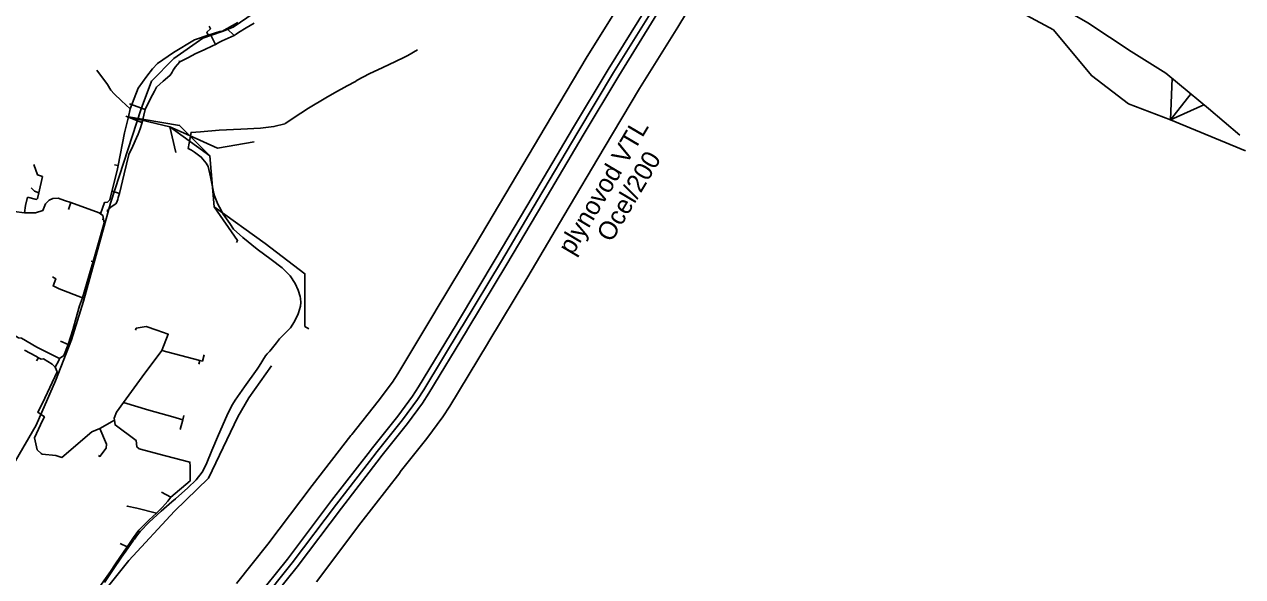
# Model space of a CAD drawing. Extents: x -555222 to -543220, y -1067119 to -1030889.
# Drawn here: x -550267 to -549473, y -1043672 to -1043312 of the extents above; entities that cross this region are included whole.
import ezdxf

# ---------------------------------------------------------------- set-up
doc = ezdxf.new("R2010")
doc.units = 0
for name, color, linetype in [('07_ELEKTRO', 7, 'Continuous'), ('07_KANALIZACE', 7, 'Continuous'), ('07_OCH_P A POPISY TI', 7, 'Continuous'), ('07_PLYNOVOD', 7, 'Continuous'), ('07_SDĚLOVACÍ', 7, 'Continuous'), ('07_VODOVOD', 7, 'Continuous')]:
    doc.layers.add(name, color=color, linetype=linetype)

msp = doc.modelspace()

# ---------------------------------------------------------------- linework, layer by layer
at = {"layer": '07_ELEKTRO'}
for points in [[(-549974.12, -1042947.84), (-549966.71, -1042973.14), (-549959.13, -1042998.29), (-549951.55, -1043025.99), (-549938.72, -1043036.58), (-549925.88, -1043047.17), (-549906.25, -1043065.21), (-549889.53, -1043077.11), (-549868.18, -1043096.69), (-549836.5, -1043125.51), (-549825.59, -1043135.37), (-549800.93, -1043157.41), (-549779.18, -1043176.38), (-549760.4, -1043193.19), (-549743.2, -1043209.09), (-549711.9, -1043227.06), (-549634.41, -1043269.38), (-549598.14, -1043296.84), (-549573.72, -1043310.9), (-549545.44, -1043329.57), (-549522.84, -1043343.61), (-549507.68, -1043356.25), (-549494.98, -1043366.73), (-549474.61, -1043384.22)], [(-550238.32, -1043706.58), (-550213.9, -1043688.03), (-550213.72, -1043680.02), (-550198.94, -1043661.37), (-550169.12, -1043629.26), (-550146.86, -1043607.87), (-550127.82, -1043567.81), (-550120.72, -1043555.47), (-550105.91, -1043534.57)]]:
    msp.add_lwpolyline(points, dxfattribs=at)
at = {"layer": '07_KANALIZACE'}
msp.add_lwpolyline([(-550272.8, -1043596.48), (-550259.34, -1043573.29), (-550246.63, -1043544.31), (-550236.16, -1043517.57), (-550228.38, -1043492.44), (-550210.77, -1043428.47), (-550190.76, -1043367.05), (-550184.19, -1043348.9), (-550169.51, -1043334.1), (-550150.59, -1043320.84), (-550138.09, -1043316.48), (-550130.78, -1043313.61), (-550098.73, -1043291.61)], dxfattribs=at)
at = {"layer": '07_OCH_P A POPISY TI'}
for p, q in [((-549812.12, -1043265.35), (-549840.9, -1043313.64)), ((-549900.02, -1043332.91), (-549875.06, -1043292.82)), ((-549886.36, -1043341.24), (-549861.4, -1043301.15)), ((-549854.56, -1043305.31), (-549879.52, -1043345.4)), ((-549840.9, -1043313.64), (-549865.86, -1043353.73)), ((-549923.29, -1043371.9), (-549900.02, -1043332.91)), ((-549909.54, -1043380.08), (-549886.36, -1043341.24)), ((-549879.52, -1043345.4), (-549902.66, -1043384.16)), ((-549865.86, -1043353.73), (-549888.91, -1043392.34)), ((-549949.61, -1043416.37), (-549923.29, -1043371.9)), ((-549935.85, -1043424.53), (-549909.54, -1043380.08)), ((-549902.66, -1043384.16), (-549928.97, -1043428.61)), ((-549888.91, -1043392.34), (-549915.21, -1043436.77)), ((-549973.12, -1043455.93), (-549949.61, -1043416.37)), ((-549959.38, -1043464.13), (-549935.85, -1043424.53)), ((-549928.97, -1043428.61), (-549952.52, -1043468.23)), ((-549915.21, -1043436.77), (-549938.78, -1043476.43)), ((-549998.44, -1043498.12), (-549973.12, -1043455.93)), ((-549984.71, -1043506.34), (-549959.38, -1043464.13)), ((-549952.52, -1043468.23), (-549977.85, -1043510.44)), ((-549938.78, -1043476.43), (-549964.12, -1043518.66)), ((-550023.55, -1043539.66), (-549999.3, -1043499.56)), ((-549999.3, -1043499.56), (-549998.44, -1043498.12)), ((-550009.97, -1043548.12), (-549985.58, -1043507.79)), ((-549985.58, -1043507.79), (-549984.71, -1043506.34)), ((-549978.72, -1043511.91), (-550003.19, -1043552.36)), ((-549977.85, -1043510.44), (-549978.72, -1043511.91)), ((-549965, -1043520.14), (-549989.61, -1043560.82)), ((-549964.12, -1043518.66), (-549965, -1043520.14)), ((-550027.08, -1043545.14), (-550023.55, -1043539.66)), ((-550036.27, -1043557.55), (-550027.08, -1043545.14)), ((-550013.9, -1043554.24), (-550009.97, -1043548.12)), ((-550023.58, -1043567.31), (-550013.9, -1043554.24)), ((-550003.19, -1043552.36), (-550007.32, -1043558.78)), ((-550053.56, -1043579.2), (-550036.27, -1043557.55)), ((-550007.32, -1043558.78), (-550017.24, -1043572.19)), ((-549989.61, -1043560.82), (-549994.14, -1043567.88)), ((-550040.9, -1043588.99), (-550023.58, -1043567.31)), ((-550017.24, -1043572.19), (-550034.58, -1043593.89)), ((-549994.14, -1043567.88), (-550004.55, -1043581.95)), ((-550079.39, -1043612.66), (-550054.14, -1043579.97)), ((-550054.14, -1043579.97), (-550053.56, -1043579.2)), ((-550004.55, -1043581.95), (-550021.92, -1043603.68)), ((-550066.67, -1043622.37), (-550041.4, -1043589.66)), ((-550035.04, -1043594.5), (-550060.31, -1043627.23)), ((-550041.4, -1043589.66), (-550040.9, -1043588.99)), ((-550034.58, -1043593.89), (-550035.04, -1043594.5)), ((-550021.92, -1043603.68), (-550022.3, -1043604.19)), ((-550022.3, -1043604.19), (-550047.59, -1043636.94)), ((-550108.15, -1043650.79), (-550079.39, -1043612.66)), ((-550095.52, -1043660.62), (-550066.67, -1043622.37)), ((-550060.31, -1043627.23), (-550089.2, -1043665.52)), ((-550047.59, -1043636.94), (-550076.57, -1043675.35)), ((-550128.66, -1043676.39), (-550108.15, -1043650.79)), ((-550116.08, -1043686.28), (-550095.52, -1043660.62)), ((-550089.2, -1043665.52), (-550109.78, -1043691.22))]:
    msp.add_line(p, q, dxfattribs=at)
at = {"layer": '07_PLYNOVOD'}
for points in [[(-550112.93, -1043688.75), (-550092.36, -1043663.07), (-550063.49, -1043624.8), (-550038.22, -1043592.08), (-550037.74, -1043591.44), (-550020.41, -1043569.75), (-550010.61, -1043556.51), (-550006.58, -1043550.24), (-549982.15, -1043509.85), (-549981.28, -1043508.39), (-549955.95, -1043466.18), (-549932.41, -1043426.57), (-549906.1, -1043382.12), (-549882.94, -1043343.32), (-549857.98, -1043303.23)], [(-550214.77, -1043675.9), (-550209.13, -1043667.34), (-550203.65, -1043659.3), (-550200.85, -1043655.38), (-550200.32, -1043654.64), (-550196.18, -1043648.86), (-550195.74, -1043648.27), (-550195.19, -1043647.51), (-550194.23, -1043646.21), (-550193.8, -1043645.56), (-550192.99, -1043644.41), (-550192.44, -1043643.71), (-550191.45, -1043642.45), (-550185.7, -1043636.47), (-550177.69, -1043629.28), (-550170.83, -1043623.22), (-550168.46, -1043621.26), (-550160.43, -1043613.99), (-550154.93, -1043608.8), (-550151.05, -1043603.86), (-550148.96, -1043599.74), (-550147.95, -1043597.83), (-550144.67, -1043589.68), (-550140.44, -1043579.45), (-550134.93, -1043567.09), (-550133.38, -1043563.95), (-550131.27, -1043559.68), (-550129.44, -1043556.94), (-550123.55, -1043548.12), (-550115.29, -1043536.72), (-550114.01, -1043534.75), (-550109.69, -1043528.1), (-550108.77, -1043526.69), (-550106.93, -1043525.06), (-550102.51, -1043519.43), (-550100.56, -1043516.95), (-550093.38, -1043509.71), (-550090.91, -1043505.65), (-550088.41, -1043500.59), (-550088.24, -1043500), (-550087.03, -1043495.69), (-550086.8, -1043493.31), (-550087.03, -1043490.65), (-550087.14, -1043489.36), (-550088.41, -1043485.24), (-550090.42, -1043480.83), (-550093.79, -1043475.94), (-550098.95, -1043470.73), (-550106.08, -1043465.1), (-550115.16, -1043458.4), (-550124.63, -1043450.95), (-550130.64, -1043445.47), (-550133.08, -1043441.77), (-550137.44, -1043435.7), (-550139.79, -1043431.11), (-550140.75, -1043429.15), (-550142.17, -1043425.95), (-550143.11, -1043423.68), (-550143.44, -1043422.18), (-550144.39, -1043417.79), (-550145.54, -1043411.22), (-550147.16, -1043404.6), (-550148.37, -1043402.38), (-550151.66, -1043398.45), (-550156.06, -1043395.28), (-550157.95, -1043393.96), (-550160.28, -1043392.8), (-550158.3, -1043382.28), (-550152.17, -1043381.84), (-550139.99, -1043380.93), (-550125.93, -1043380.12), (-550112.98, -1043379.6), (-550104.3, -1043378.53), (-550097.23, -1043376.81), (-550096.89, -1043376.58), (-550096.52, -1043376.33), (-550095.59, -1043375.7), (-550086.77, -1043369.73), (-550081.7, -1043366.51), (-550070.45, -1043359.82), (-550064.7, -1043356.41), (-550056.51, -1043352), (-550051.16, -1043349.04), (-550049.98, -1043348.35), (-550042.21, -1043344.17), (-550033.29, -1043339.99), (-550024.95, -1043336.18), (-550019.07, -1043333.29), (-550016.9, -1043332.18), (-550010.68, -1043328.58)]]:
    msp.add_lwpolyline(points, dxfattribs=at)
at = {"layer": '07_SDĚLOVACÍ'}
for points in [[(-549547.17, -1043363.74), (-549571.37, -1043345.27), (-549596.17, -1043315.4), (-549628.09, -1043298.18), (-549661.97, -1043280.56), (-549692.76, -1043263.98), (-549729.65, -1043243.29)], [(-550146.39, -1043313.14), (-550145.53, -1043314.68), (-550147.97, -1043317.06), (-550147.19, -1043318.99)], [(-550138.82, -1043316.27), (-550147.19, -1043318.99)], [(-550147.19, -1043318.99), (-550138.82, -1043316.27)], [(-550146.39, -1043313.14), (-550146.43, -1043313.05)], [(-550138.82, -1043316.27), (-550138.17, -1043316.46), (-550127.84, -1043310.69)], [(-550197.95, -1043366.94), (-550192.73, -1043353.5), (-550187.04, -1043345.62), (-550183.37, -1043340.89), (-550180.17, -1043337.5), (-550169.73, -1043330.27), (-550156.1, -1043321.89), (-550147.19, -1043318.99)], [(-550197.95, -1043366.94), (-550203.62, -1043361.83), (-550208.44, -1043357.21), (-550210.62, -1043354.82), (-550212.86, -1043351.14), (-550219.75, -1043341.73)], [(-550187.04, -1043345.62), (-550183.37, -1043340.89)], [(-549519.77, -1043374.06), (-549518.7, -1043347.01)], [(-550208.44, -1043357.21), (-550210.62, -1043354.82)], [(-550197.95, -1043366.94), (-550192.73, -1043353.5)], [(-549519.77, -1043374.06), (-549506.27, -1043356.9)], [(-549519.77, -1043374.06), (-549547.17, -1043363.74)], [(-549519.77, -1043374.06), (-549498.07, -1043364.39)], [(-550205.78, -1043403.99), (-550201.59, -1043382.56), (-550199.03, -1043372.24)], [(-550199.03, -1043372.24), (-550200.33, -1043371.87)], [(-550200.33, -1043371.87), (-550165.73, -1043377.77), (-550159.28, -1043384.3)], [(-550200.33, -1043371.87), (-550172.16, -1043378.59)], [(-550199.03, -1043372.24), (-550197.95, -1043366.94)], [(-550172.16, -1043378.59), (-550146.06, -1043397.67)], [(-550172.16, -1043378.59), (-550159.28, -1043384.3)], [(-550172.16, -1043378.59), (-550168.15, -1043395.52)], [(-549519.77, -1043374.06), (-549470.94, -1043394.23)], [(-550159.28, -1043384.3), (-550141.03, -1043392.58), (-550117.18, -1043388.44)], [(-550159.28, -1043384.3), (-550146.06, -1043397.67)], [(-550257.57, -1043421.68), (-550255.25, -1043411.13), (-550258.42, -1043409.93), (-550260.69, -1043403.25)], [(-550217.33, -1043435.43), (-550214.83, -1043428.06), (-550212.78, -1043427.75), (-550211.36, -1043426.26), (-550206.18, -1043406.06), (-550205.78, -1043403.99)], [(-550205.78, -1043403.99), (-550208.19, -1043403.57)], [(-550205.78, -1043403.99), (-550208.19, -1043403.57)], [(-550146.06, -1043397.67), (-550143.29, -1043430.83)], [(-550257.57, -1043421.68), (-550260.44, -1043420.6), (-550262.62, -1043418.41)], [(-550266.96, -1043434.75), (-550266.24, -1043430.01), (-550264.95, -1043424.51)], [(-550266.96, -1043434.75), (-550259.62, -1043434.78), (-550254.87, -1043433.21), (-550253.12, -1043428.8), (-550250.82, -1043426.49), (-550248.36, -1043425.46), (-550245.03, -1043425.12), (-550240.73, -1043426.62), (-550236.64, -1043427.98)], [(-550264.95, -1043424.51), (-550259.16, -1043426.07), (-550258.3, -1043425.44), (-550257.57, -1043421.68)], [(-550240.73, -1043426.62), (-550236.64, -1043427.98)], [(-550236.64, -1043427.98), (-550238.18, -1043432.53)], [(-550217.33, -1043435.43), (-550218.14, -1043434.82), (-550236.64, -1043427.98)], [(-550236.64, -1043427.98), (-550218.14, -1043434.82), (-550217.33, -1043435.43)], [(-550214.83, -1043428.06), (-550217.33, -1043435.43)], [(-550280.5, -1043432.39), (-550273.57, -1043433.86), (-550266.96, -1043434.75)], [(-550266.24, -1043430.01), (-550266.96, -1043434.75)], [(-550217.33, -1043435.43), (-550215.84, -1043436.48), (-550215.29, -1043438.95)], [(-550143.29, -1043430.83), (-550128, -1043452.89), (-550128.64, -1043454.18)], [(-550143.29, -1043430.83), (-550109.9, -1043454.69), (-550084.1, -1043474.52), (-550084.12, -1043508.88), (-550081.62, -1043510.3)], [(-550215.29, -1043438.95), (-550215.01, -1043441.25), (-550219.54, -1043457.28), (-550222.17, -1043466.55)], [(-550215.29, -1043438.95), (-550216.15, -1043439.13)], [(-550222.17, -1043466.55), (-550224.45, -1043474.6), (-550229.15, -1043490.23)], [(-550222.17, -1043466.55), (-550223.47, -1043466.18)], [(-550229.15, -1043490.23), (-550244.34, -1043484.33), (-550248.29, -1043482.46), (-550246.48, -1043477.77), (-550248.55, -1043476.48)], [(-550229.15, -1043490.23), (-550231, -1043495.37)], [(-550231, -1043495.37), (-550231.44, -1043496.96), (-550235.32, -1043510.96), (-550238.39, -1043520.61)], [(-550238.39, -1043520.61), (-550235.32, -1043510.96), (-550231.44, -1043496.96)], [(-550294.84, -1043504.75), (-550282.99, -1043510.2), (-550273.51, -1043514.6), (-550270.76, -1043516.29), (-550268.76, -1043516.39), (-550258.81, -1043522.31), (-550244.14, -1043529.77)], [(-550187.57, -1043508.85), (-550194.03, -1043509.97), (-550194.52, -1043511.28)], [(-550177.46, -1043524.55), (-550173.13, -1043513.89), (-550180.67, -1043511.22), (-550187.57, -1043508.85)], [(-550266.98, -1043524.25), (-550259.46, -1043528.28)], [(-550244.14, -1043529.77), (-550241.25, -1043527.76), (-550238.39, -1043520.61)], [(-550238.39, -1043520.61), (-550241.25, -1043527.76), (-550244.14, -1043529.77)], [(-550238.39, -1043520.61), (-550243.38, -1043518.41)], [(-550202.43, -1043558.52), (-550190.13, -1043541.61), (-550177.91, -1043525.45), (-550177.46, -1043524.55)], [(-550177.46, -1043524.55), (-550152.62, -1043530.99)], [(-550259.46, -1043528.28), (-550257.73, -1043529.21)], [(-550257.73, -1043529.21), (-550258.96, -1043531.22)], [(-550257.73, -1043529.21), (-550255.99, -1043530.23), (-550254.39, -1043529.98), (-550248.84, -1043533.53), (-550246.96, -1043535.48)], [(-550244.14, -1043529.77), (-550244.56, -1043531.01), (-550246.96, -1043535.48)], [(-550246.96, -1043535.48), (-550244.56, -1043531.01)], [(-550152.62, -1043530.99), (-550153.14, -1043533.36)], [(-550152.62, -1043530.99), (-550150.94, -1043531.43), (-550149.84, -1043527.32)], [(-550246.96, -1043535.48), (-550245.65, -1043538.5), (-550255.25, -1043558.94), (-550258.24, -1043564.77), (-550253.87, -1043567.81), (-550255.04, -1043570.27)], [(-550208.23, -1043569.93), (-550208.38, -1043568.59), (-550206.99, -1043564.64), (-550202.43, -1043558.52)], [(-550202.43, -1043558.52), (-550185.82, -1043563.54), (-550170.29, -1043567.84), (-550163.66, -1043569.67)], [(-550255.04, -1043570.27), (-550260.38, -1043581.51), (-550258.6, -1043589.4), (-550256.04, -1043591.68), (-550255.35, -1043592.1), (-550246.52, -1043592.98), (-550242.53, -1043594.21), (-550223.02, -1043577.51), (-550217.79, -1043575.43)], [(-550258.24, -1043564.77), (-550253.87, -1043567.81)], [(-550217.79, -1043575.43), (-550208.23, -1043569.93)], [(-550217.79, -1043575.43), (-550208.23, -1043569.93)], [(-550207.92, -1043569.89), (-550208.23, -1043569.93)], [(-550208.23, -1043569.93), (-550207.87, -1043573.07), (-550194.14, -1043583.12), (-550193.6, -1043587.41), (-550192.16, -1043588.55), (-550175, -1043593.12), (-550159.02, -1043597.27), (-550158.81, -1043600.03), (-550158.94, -1043609.52), (-550171.49, -1043620.22)], [(-550163.66, -1043569.67), (-550165.39, -1043576.11)], [(-550162.94, -1043567.02), (-550163.66, -1043569.67)], [(-550217.79, -1043575.43), (-550213.42, -1043585.62), (-550213.59, -1043588.24), (-550217.71, -1043593.57), (-550218.71, -1043592.9)], [(-550194.14, -1043583.12), (-550193.6, -1043587.41)], [(-550255.35, -1043592.1), (-550246.52, -1043592.98)], [(-550171.49, -1043620.22), (-550177.54, -1043616.81)], [(-550180.9, -1043630.54), (-550193.58, -1043627.42), (-550199.86, -1043626.02), (-550199.94, -1043626.31)], [(-550171.49, -1043620.22), (-550173.49, -1043622.68), (-550176.91, -1043626.62), (-550180.9, -1043630.54)], [(-550173.49, -1043622.68), (-550176.91, -1043626.62)], [(-550180.9, -1043630.54), (-550185.67, -1043634.85), (-550192.36, -1043641.65), (-550195.82, -1043646.37), (-550198.89, -1043650.94), (-550199.87, -1043652.46)], [(-550180.9, -1043630.54), (-550185.67, -1043634.85)], [(-550204.59, -1043650.41), (-550199.87, -1043652.46)], [(-550195.82, -1043646.37), (-550198.89, -1043650.94)], [(-550199.87, -1043652.46), (-550207.52, -1043663.59), (-550210.8, -1043668.62), (-550219.9, -1043681.54), (-550225.07, -1043684.67), (-550232.65, -1043695.7)], [(-550210.8, -1043668.62), (-550207.52, -1043663.59)]]:
    msp.add_lwpolyline(points, dxfattribs=at)
at = {"layer": '07_VODOVOD'}
for p, q in [((-550130.26, -1043319.18), (-550134.76, -1043314.84)), ((-550142.39, -1043324.9), (-550145.34, -1043318.87)), ((-550170.57, -1043343.09), (-550169.88, -1043341.83)), ((-550169.88, -1043341.83), (-550168.65, -1043339.79)), ((-550166.05, -1043335.96), (-550166.17, -1043335.8)), ((-550165.68, -1043336.35), (-550166.05, -1043335.96)), ((-550188.32, -1043367.42), (-550198.54, -1043363.6)), ((-550190.35, -1043375.8), (-550200.72, -1043371.82)), ((-550190.35, -1043376.43), (-550190.35, -1043375.8)), ((-550190.06, -1043374.8), (-550189.62, -1043374.89)), ((-550204.97, -1043422.06), (-550209.63, -1043420.54)), ((-550207.39, -1043428.95), (-550206.9, -1043428.25)), ((-550206.9, -1043428.25), (-550206.39, -1043427.16)), ((-550212.85, -1043433.28), (-550213.16, -1043433.25)), ((-550212.79, -1043433.84), (-550213.07, -1043433.82)), ((-550212.79, -1043433.84), (-550212.86, -1043433.65)), ((-550212.68, -1043433.4), (-550212.85, -1043433.28))]:
    msp.add_line(p, q, dxfattribs=at)
msp.add_lwpolyline([(-550212.91, -1043434.37), (-550212.85, -1043434.1), (-550212.79, -1043433.84), (-550212.74, -1043433.62), (-550212.68, -1043433.4), (-550212.3, -1043432.72), (-550211.93, -1043432.05), (-550209.66, -1043430.5), (-550207.39, -1043428.95), (-550206.9, -1043428.25), (-550206.39, -1043427.16), (-550206.08, -1043426), (-550205.76, -1043424.85), (-550205.36, -1043423.46), (-550204.97, -1043422.06), (-550201.89, -1043409.44), (-550198.81, -1043396.83), (-550196.35, -1043391.38), (-550193.89, -1043385.92), (-550192.77, -1043383.48), (-550191.56, -1043379.96), (-550190.35, -1043376.43), (-550190.25, -1043375.84), (-550190.14, -1043375.36), (-550190.02, -1043374.87), (-550189.17, -1043371.14), (-550188.32, -1043367.42), (-550186.58, -1043363.66), (-550183.5, -1043357.93), (-550182.16, -1043355.34), (-550180.83, -1043352.74), (-550176.44, -1043349), (-550172.05, -1043345.26), (-550171.31, -1043344.18), (-550170.57, -1043343.09), (-550169.88, -1043341.83), (-550169.26, -1043340.81), (-550168.65, -1043339.79), (-550167.16, -1043338.07), (-550165.68, -1043336.35), (-550160.42, -1043333.6), (-550155.15, -1043330.86), (-550149.7, -1043328.38), (-550144.26, -1043325.9), (-550142.39, -1043324.9), (-550140.18, -1043323.8), (-550137.98, -1043322.71), (-550134.12, -1043320.94), (-550130.26, -1043319.18), (-550128.86, -1043318.21), (-550127.46, -1043317.24), (-550122.28, -1043314.2), (-550117.09, -1043311.16)], dxfattribs=at)

# ---------------------------------------------------------------- texts
at = {"layer": '07_OCH_P A POPISY TI'}
for s, rotation, p in [('plynovod VTL', 59.3787, (-549909.54, -1043462.95)), ('Ocel/200', 59.27722, (-549884.3, -1043454.55))]:
    msp.add_text(s, height=12, rotation=rotation, dxfattribs=at).set_placement(p)

doc.saveas('drawing.dxf')
